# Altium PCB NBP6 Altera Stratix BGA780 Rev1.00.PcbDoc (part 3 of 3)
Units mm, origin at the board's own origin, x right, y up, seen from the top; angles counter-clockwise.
Board outline 69 x 80.99 mm, 6 copper layers (Top Layer, Upper, lower, VCC_PLANE, GND_PLANE, Bottom Layer); 92 components, 279 nets, 1271 pads, 560 vias.
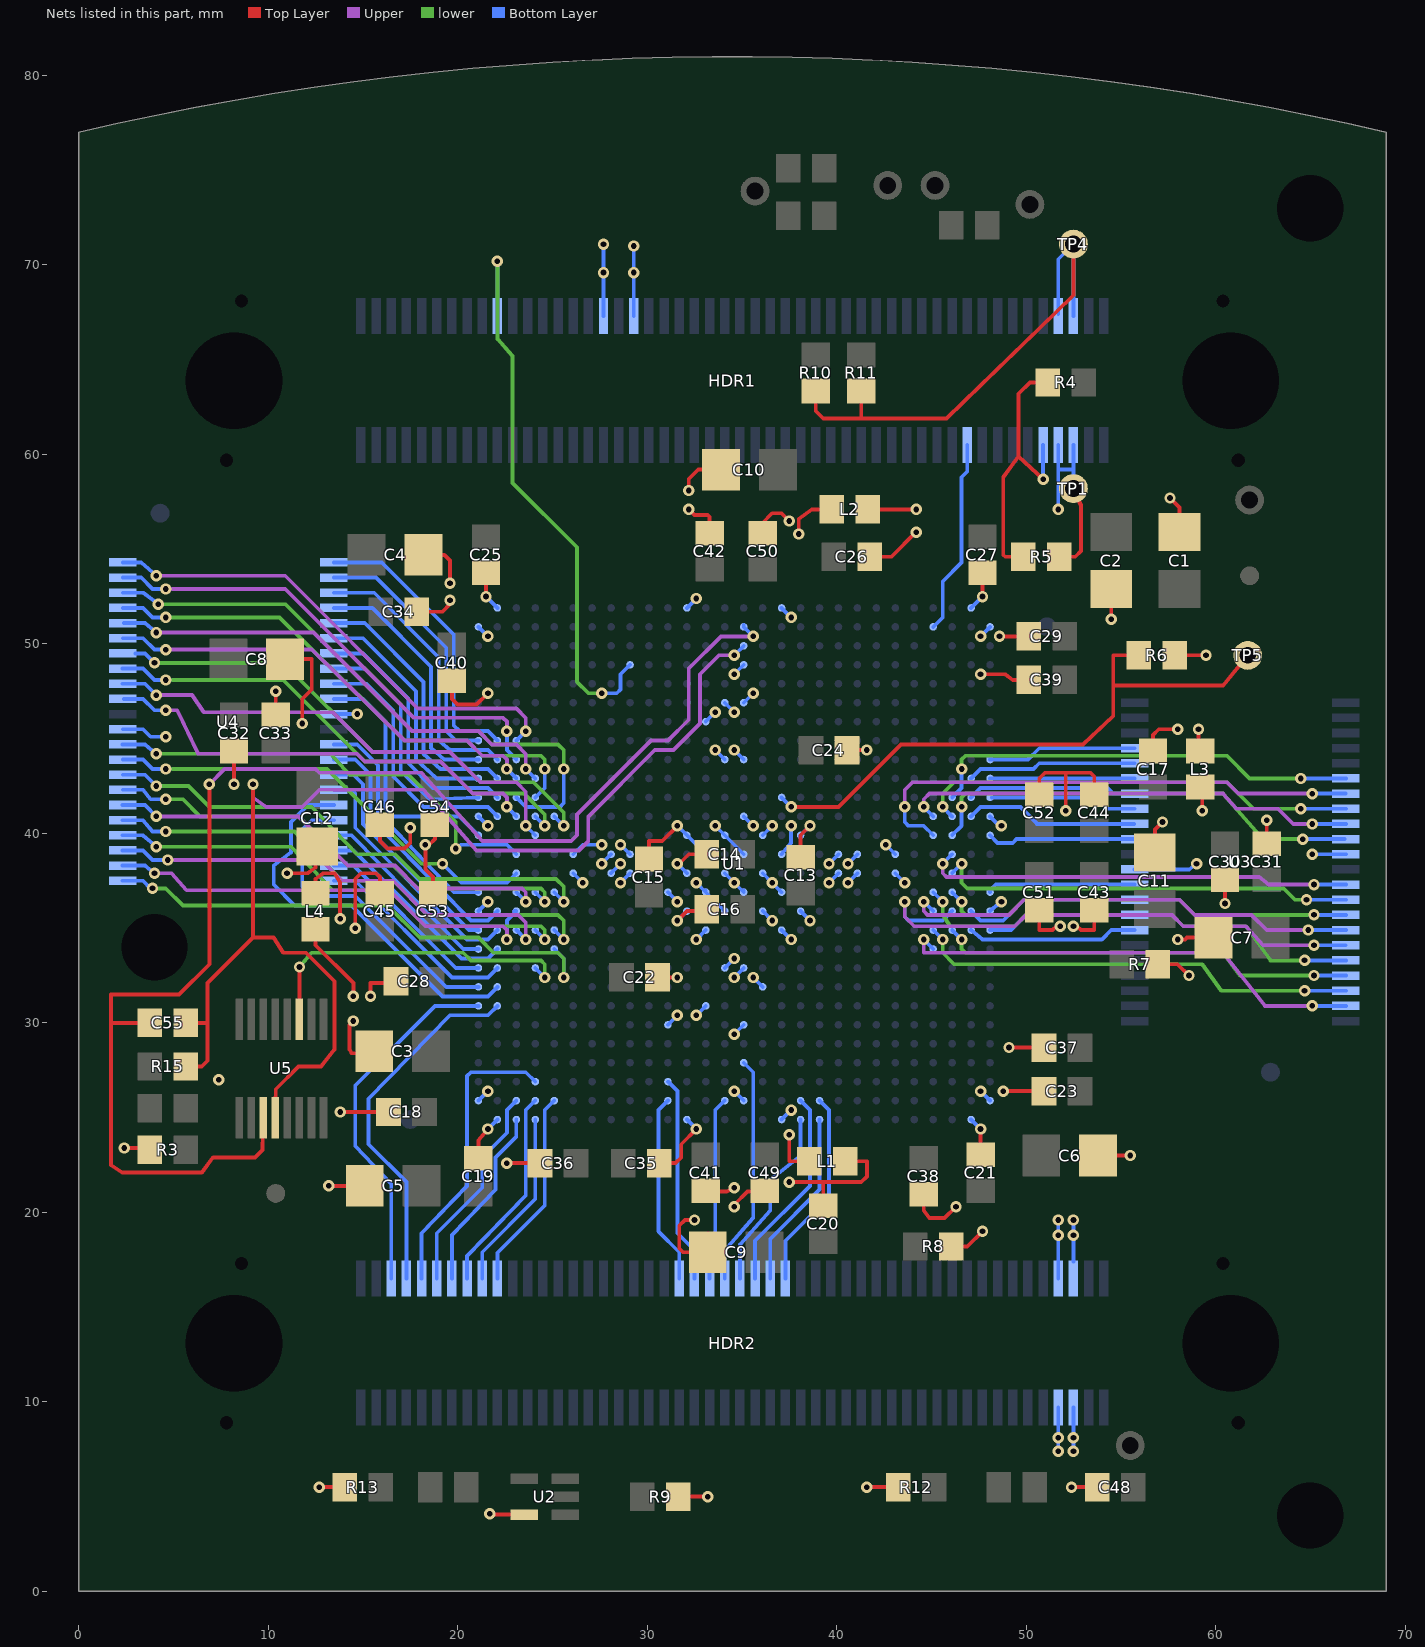
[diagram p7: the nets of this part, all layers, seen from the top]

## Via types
v1: diameter 0.6, hole 0.3, Top Layer to Bottom Layer, 560 vias

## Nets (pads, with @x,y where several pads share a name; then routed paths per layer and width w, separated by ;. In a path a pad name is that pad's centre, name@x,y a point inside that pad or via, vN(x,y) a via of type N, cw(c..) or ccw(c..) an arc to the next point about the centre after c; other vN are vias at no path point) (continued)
SRAM0_A15: U1.W4 U3.21 | length 25.1
  Upper w0.2: v1(44.6,34.4) 44.6,33.7 60.4,33.7 62.6,30.9 v1(65.1,30.9)
  Bottom Layer w0.2: v1(44.6,34.4) U1.W4@45.1,33.9 ; v1(65.1,30.9) U3.21@66.9,30.9
SRAM0_A16: U1.V4 U3.20 | length 23.9
  lower w0.2: v1(45.6,34.4) 45.6,33.7 46.2,33.1 59.3,33.1 60.3,31.7 v1(64.7,31.7)
  Bottom Layer w0.2: U1.V4@45.1,34.9 v1(45.6,34.4) ; v1@64.5,31.7 U3.20@66.9,31.7
SRAM0_A17: U1.V3 U3.19 | length 22.2
  lower w0.2: v1(46.6,34.4) 46.6,33.9 46.8,33.7 60.4,33.7 61.3,32.5 v1(65.2,32.5)
  Bottom Layer w0.2: U1.V3@46.1,34.9 v1(46.6,34.4) ; v1(65.2,32.5) U3.19@66.9,32.5
SRAM0_A18: U1.T4 U3.18 | length 24.4
  lower w0.2: v1(45.6,36.4) 45.6,35.7 46,35.1 49.4,35.1 50,35.7 57.7,35.7 58.3,35.1 61.6,35.1 62.9,33.3 v1(64.7,33.3)
  Bottom Layer w0.2: U1.T4@45.1,36.9 v1(45.6,36.4) ; v1(64.7,33.3) U3.18@66.9,33.3
SRAM0_D0: U1.N4 U3.7 | length 27.2
  Upper w0.2: v1(43.6,41.4) 43.6,42.3 44,42.7 60.6,42.7 61.2,42.1 v1(65.1,42.1)
  Bottom Layer w0.2: v1(43.6,41.4) 43.6,40.6 43.8,40.4 44.6,40.4 U1.N4@45.1,39.9 ; v1(65.1,42.1) U3.7@66.875,42.1
SRAM0_D1: U1.M3 U3.8 | length 23.5
  lower w0.2: v1(45.6,41.4) 45.6,42.1 46.2,42.7 60.6,42.7 62,41.3 v1(64.5,41.3)
  Bottom Layer w0.2: v1(45.6,41.4) U1.M3@46.1,40.9 ; v1(64.5,41.3) U3.8@66.9,41.3
SRAM0_D2: U1.M4 U3.9 | length 24.2
  Upper w0.2: v1(44.6,41.4) 44.6,41.8 44.9,42.1 60.4,42.1 61.1,41.3 63.3,41.3 64.1,40.5 v1(65.1,40.5)
  Bottom Layer w0.2: v1(44.6,41.4) U1.M4@45.1,40.9 ; v1(65.1,40.5) U3.9@66.9,40.5
SRAM0_D3: U1.N3 U3.10 | length 23.6
  lower w0.2: v1(46.6,41.4) 46.6,41.9 46.8,42.1 60.4,42.1 62.5,39.7 v1(64.6,39.7)
  Bottom Layer w0.2: U1.N3@46.1,39.9 46.6,40.4 v1(46.6,41.4) ; v1(64.6,39.7) U3.10@66.8,39.7
SRAM0_D4: U1.P3 U3.13 | length 22.7
  Upper w0.2: v1(45.6,38.4) 45.6,37.9 45.8,37.7 62.3,37.7 62.8,37.3 v1(65.2,37.3)
  Bottom Layer w0.2: v1(45.6,38.4) U1.P3@46.1,38.9 ; v1(65.2,37.3) U3.13@66.9,37.3
SRAM0_D5: U1.R3 U3.14 | length 22.4
  lower w0.2: v1(46.6,38.4) 46.6,37.4 46.9,37.1 63.6,37.1 64.2,36.5 v1(64.8,36.5)
  Bottom Layer w0.2: U1.R3@46.1,37.9 v1(46.6,38.4) ; v1(64.8,36.5) U3.14@66.9,36.5
SRAM0_D6: U1.T3 U3.15 | length 22.3
  lower w0.2: v1(46.6,36.4) 46.6,35.9 46.8,35.7 49.1,35.7 49.9,36.5 58.1,36.5 58.9,35.7 v1(65.2,35.7)
  Bottom Layer w0.2: U1.T3@46.1,36.9 v1(46.6,36.4) ; v1(65.2,35.7) U3.15@66.9,35.7
SRAM0_D7: U1.U4 U3.16 | length 24.6
  Upper w0.2: v1(44.6,36.4) 44.6,35.9 44.8,35.7 49.1,35.7 49.9,36.5 58.1,36.5 58.9,35.7 61.9,35.7 62.7,34.9 v1@64.7,34.9
  Bottom Layer w0.2: v1(44.6,36.4) U1.U4@45.1,35.9 ; v1@64.7,34.9 U3.16@66.9,34.9
  other v1: 64.9,34.9
SRAM0_D8: U1.V2 U3.29 | length 9
  Bottom Layer w0.2: U1.V2@47.1,34.9 47.7,34.4 54,34.4 54.5,34.9 U3.29@55.725,34.9
SRAM0_D9: U1.V1 U3.30 | length 8
  Bottom Layer w0.2: U1.V1@48.1,34.9 49.2,34.9 50,35.7 U3.30@55.725,35.7
SRAM0_D10: U1.U2 U3.31 | length 9.3
  Bottom Layer w0.2: U1.U2@47.1,35.9 47.6,35.4 48.8,35.4 49.9,36.5 U3.31@55.725,36.5
SRAM0_D11: U1.T1 U3.32 | length 7.8
  Bottom Layer w0.2: U1.T1@48.1,36.9 48.1,37 48.4,37.3 U3.32@55.725,37.3
SRAM0_D12: U1.N1 U3.35 | length 7.9
  Bottom Layer w0.2: U1.N1@48.1,39.9 48.5,39.5 49.3,39.5 49.5,39.7 55.625,39.7 U3.35@55.725,39.7
SRAM0_D13: U1.M2 U3.36 | length 9.2
  Bottom Layer w0.2: U1.M2@47.1,40.9 47.6,41.4 49.7,41.4 50.6,40.5 ; 50.575,40.5 U3.36@55.7,40.5
SRAM0_D14: U1.L1 U3.37 | length 7.8
  Bottom Layer w0.2: U1.L1@48.2,41.9 53.7,41.9 54.3,41.3 U3.37@55.725,41.3
SRAM0_D15: U1.L2 U3.38 | length 9
  Bottom Layer w0.2: U1.L2@47.1,41.9 47.6,42.4 54.3,42.4 54.6,42.1 U3.38@55.725,42.1
SRAM0_E: U1.L3 U3.6 | length 23.1
  lower w0.2: v1(46.6,43.4) 46.6,43.9 46.8,44.1 60.6,44.1 61.8,42.9 v1(64.5,42.9)
  Bottom Layer w0.2: U1.L3@46.1,41.9 46.6,42.4 v1(46.6,43.4) ; v1(64.5,42.9) U3.6@66.9,42.9
SRAM0_LB: U1.K1 U3.39 | length 7.6
  Bottom Layer w0.2: U1.K1@48.1,42.9 U3.39@55.725,42.9
SRAM0_OE: U1.J1 U3.41 | length 7.9
  Bottom Layer w0.2: U1.J1@48.1,43.9 50.1,43.9 50.7,44.5 U3.41@55.725,44.5
SRAM0_UB: U1.K2 U3.40 | length 9
  Bottom Layer w0.2: U1.K2@47.1,42.9 47.6,43.4 50.4,43.4 50.7,43.7 U3.40@55.725,43.7
SRAM0_W: U1.U3 U3.17 | length 28.8
  Upper w0.2: v1(43.6,36.4) 43.6,35.6 44.1,35.1 49.4,35.1 50,35.7 57.7,35.7 58.3,35.1 61.6,35.1 62.5,34.1 v1(65.2,34.1)
  Bottom Layer w0.2: v1(43.6,36.4) 43.6,35.6 43.8,35.4 45.6,35.4 U1.U3@46.1,35.9 ; v1(65.2,34.1) U3.17@66.875,34.1
SRAM1_A0: U1.K27 U4.5 | length 14.2
  Bottom Layer w0.2: U4.5@13.475,51.1 15.1,51.1 18.2,48 18.2,44.2 19.1,43.4 21.6,43.4 U1.K27@22.1,42.9
SRAM1_A1: U1.J28 U4.4 | length 13.4
  Bottom Layer w0.2: U4.4@13.475,51.9 15.5,51.9 18.6,48.8 18.6,44.5 19.3,43.9 U1.J28@21.1,43.9
SRAM1_A2: U1.J27 U4.3 | length 14.8
  Bottom Layer w0.2: U4.3@13.475,52.7 15.6,52.7 19,49.3 19,44.9 19.6,44.4 21.6,44.4 U1.J27@22.1,43.9
SRAM1_A3: U1.H28 U4.2 | length 13.8
  Bottom Layer w0.2: U4.2@13.475,53.5 15.7,53.5 19.4,49.8 19.4,45.4 19.9,44.9 U1.H28@21.1,44.9
SRAM1_A4: U1.H27 U4.1 | length 15.3
  Bottom Layer w0.2: U4.1@13.475,54.3 16,54.3 19.8,50.5 19.8,45.7 20.1,45.4 21.6,45.4 U1.H27@22.1,44.9
SRAM1_A5: U1.H26 U4.44 | length 26.1
  Upper w0.2: v1(4.1,53.6) 10.9,53.6 17.9,46.6 23.1,46.6 23.6,46.1 v1(23.6,45.4)
  Bottom Layer w0.2: U4.44@2.325,54.3 3.3,54.3 v1(4.1,53.6) ; U1.H26@23.1,44.9 v1(23.6,45.4)
SRAM1_A6: U1.J26 U4.43 | length 25.7
  Top Layer w0.2: v1(4.6,52.9) v1@4.7,52.9
  Upper w0.2: v1(4.6,52.9) 10.9,52.9 17.7,46.1 22.4,46.1 22.6,45.9 v1(22.6,45.4)
  Bottom Layer w0.2: U4.43@2.325,53.5 3.3,53.5 3.9,52.9 v1(4.6,52.9) ; v1(22.6,45.4) 22.6,44.4 U1.J26@23.1,43.9
SRAM1_A7: U1.L26 U4.42 | length 32.2
  lower w0.2: v1(4.2,52.1) 10.9,52.1 17.6,45.4 21.1,45.4 21.8,44.7 25.3,44.7 25.6,44.4 v1(25.6,43.4)
  Bottom Layer w0.2: U4.42@2.325,52.7 3.4,52.7 v1(4.2,52.1) ; U1.L26@23.1,41.9 23.6,41.4 25.4,41.4 25.6,41.6 v1@25.6,43.3
SRAM1_A8: U1.T26 U4.28 | length 24.4
  Upper w0.2: v1(4.1,40.9) 8.9,40.9 11.6,40.9 14.2,38.3 16.7,38.3 17.9,37.1 23.4,37.1 23.6,36.9 v1(23.6,36.4)
  Bottom Layer w0.2: U4.28@2.3,41.5 3.5,41.5 v1(4.1,40.9) ; U1.T26@23.1,36.9 v1(23.6,36.4)
SRAM1_A9: U1.V24 U4.27 | length 27.3
  lower w0.2: v1(4.6,40.1) 11.4,40.1 13.9,37.5 16.6,37.5 18.4,35.7 25.3,35.7 25.6,35.4 v1(25.6,34.4)
  Bottom Layer w0.2: U4.27@2.3,40.7 3.4,40.7 3.9,40.1 v1(4.6,40.1) ; U1.V24@25.1,34.9 v1(25.6,34.4)
SRAM1_A10: U1.V25 U4.26 | length 25.6
  lower w0.2: v1(4.1,39.3) 11.2,39.3 13.4,37 16.4,37 18.3,35.1 24.4,35.1 24.6,34.9 v1(24.6,34.4)
  Bottom Layer w0.2: U4.26@2.3,39.9 3.4,39.9 v1(4.1,39.3) ; U1.V25@24.1,34.9 v1(24.6,34.4)
SRAM1_A11: U1.V26 U4.25 | length 24.5
  Upper w0.2: v1(4.7,38.6) 12.8,38.6 13.9,37.5 16.6,37.5 18.4,35.7 23.2,35.7 23.6,35.3 v1(23.6,34.4)
  Bottom Layer w0.2: U4.25@2.3,39.1 3.4,39.1 3.9,38.6 v1(4.7,38.6) ; U1.V26@23.1,34.9 v1(23.6,34.4)
SRAM1_A12: U1.U26 U4.24 | length 24
  Upper w0.2: v1(4,37.9) 4.9,37.9 5.7,37 12.9,37 16.4,37 18.3,35.1 22.4,35.1 22.6,34.9 v1(22.6,34.4)
  Bottom Layer w0.2: U4.24@2.3,38.3 3.5,38.3 v1(4,37.9) ; v1(22.6,34.4) 22.6,35.4 U1.U26@23.1,35.9 U1.U26@23,35.9
SRAM1_A13: U1.W24 U4.23 | length 35.9
  lower w0.2: v1(3.9,37.1) 4.6,37.1 5.5,36.2 16.3,36.2 ; v1(25.6,32.4) 25.6,33.4 25.3,33.7 21.9,33.7 21.1,34.5 18,34.5 16.3,36.2 ; 16.3,36.2 12.2,36.2 16.3,36.2
  Bottom Layer w0.2: U4.23@2.3,37.5 3.4,37.5 3.8,37.1 v1(3.9,37.1) ; U1.W24@25.1,33.9 25.6,33.4 v1(25.6,32.4)
SRAM1_A14: U1.Y27 U4.22 | length 10.9
  Bottom Layer w0.2: U4.22@13.475,37.5 14.6,37.5 19.7,32.4 21.6,32.4 U1.Y27@22.1,32.9
SRAM1_A15: U1.Y28 U4.21 | length 9.9
  Bottom Layer w0.2: U4.21@13.475,38.3 14.5,38.3 19.9,32.9 U1.Y28@21.1,32.9
SRAM1_A16: U1.W27 U4.20 | length 11.2
  Bottom Layer w0.2: U4.20@13.475,39.1 14.5,39.1 20.2,33.4 21.6,33.4 U1.W27@22.1,33.9
SRAM1_A17: U1.W28 U4.19 | length 10.1
  Bottom Layer w0.2: U4.19@13.475,39.9 13.575,39.9 14.4,39.9 20.3,33.9 U1.W28@21.1,33.9
SRAM1_A18: U1.AA28 U4.18 | length 16.4
  Bottom Layer w0.2: U4.18@13.475,40.7 12.3,40.7 11.8,40.2 11.8,37.2 12.275,36.725 12.275,36.7 14.6,36.7 19.4,31.9 U1.AA28@21.1,31.9
SRAM1_D0: U1.L27 U4.7 | length 13.8
  Bottom Layer w0.2: U4.7@13.475,49.5 15,49.5 17.4,47.1 17.4,43.7 18.7,42.4 21.6,42.4 U1.L27@22.1,41.9
SRAM1_D1: U1.L28 U4.8 | length 12.5
  Bottom Layer w0.2: U4.8@13.475,48.7 15.1,48.7 17,46.8 17,43.3 18.5,41.8 U1.L28@21.1,41.9
SRAM1_D2: U1.M27 U4.9 | length 13.6
  Bottom Layer w0.2: U4.9@13.475,47.9 15.2,47.9 16.6,46.5 16.6,43 18.2,41.4 21.6,41.4 U1.M27@22.1,40.9
SRAM1_D3: U1.N28 U4.10 | length 13.3
  Bottom Layer w0.2: U4.10@13.475,47.1 15,47.1 16.2,45.9 16.2,41.3 16.6,40.9 20.1,40.9 U1.N28@21.1,39.9
SRAM1_D4: U1.T28 U4.13 | length 12.4
  Bottom Layer w0.2: U4.13@13.475,44.7 14.7,44.7 15.8,43.6 15.8,41.1 19.8,36.9 U1.T28@21.1,36.9
SRAM1_D5: U1.U27 U4.14 | length 13.7
  Bottom Layer w0.2: U4.14@13.475,43.9 14.6,43.9 15.4,43.1 15.4,40.8 20.7,35.4 21.6,35.4 U1.U27@22.1,35.9
SRAM1_D6: U1.V28 U4.15 | length 12.3
  Bottom Layer w0.2: U4.15@13.475,43.1 14.5,43.1 15,42.6 15,40.5 20.6,34.9 U1.V28@21.1,34.9
SRAM1_D7: U1.V27 U4.16 | length 13.2
  Bottom Layer w0.2: U4.16@13.475,42.3 14.4,42.3 14.6,42.1 14.6,40.3 20.5,34.4 21.6,34.4 U1.V27@22.1,34.9
SRAM1_D8: U1.T25 U4.29 | length 25.7
  lower w0.2: v1(4.6,41.8) 5.5,41.8 6.4,40.9 11.6,40.9 14.2,38.3 16.6,38.3 17.9,37.1 24.4,37.1 24.6,36.9 v1(24.6,36.4)
  Bottom Layer w0.2: U4.29@2.325,42.3 3.4,42.3 3.8,41.8 v1(4.6,41.8) ; U1.T25@24.1,36.9 v1(24.6,36.4)
SRAM1_D9: U1.T24 U4.30 | length 27.3
  lower w0.2: v1(4.1,42.5) 5.8,42.5 6.9,41.4 12.3,41.4 14.7,38.9 16.7,38.9 18,37.6 25.2,37.6 25.6,37.2 v1(25.6,36.4)
  Bottom Layer w0.2: U4.30@2.325,43.1 3.5,43.1 v1(4.1,42.5) ; U1.T24@25.1,36.9 v1(25.6,36.4)
SRAM1_D10: U1.R26 U4.31 | length 23.7
  lower w0.2: v1(4.6,43.4) 13.1,43.4 18.1,38.4 v1(19.2,38.4)
  Bottom Layer w0.2: U4.31@2.325,43.9 3.4,43.9 3.9,43.4 v1(4.6,43.4) ; v1(19.2,38.4) 20.2,37.4 22.6,37.4 U1.R26@23.1,37.9
SRAM1_D11: U1.P26 U4.32 | length 24.2
  lower w0.2: v1(4.1,44.2) 13.3,44.2 14.3,43.1 17.4,43.1 19.9,40.6 v1(19.9,39.2)
  Bottom Layer w0.2: U4.32@2.3,44.7 3.5,44.7 v1(4.1,44.2) ; v1(19.9,39.2) 20.2,39.4 22.6,39.4 U1.P26@23.1,38.9
SRAM1_D12: U1.M26 U4.35 | length 24
  Upper w0.2: v1@4.584,46.516 4.6,46.516 5.2,46.5 6.3,44.2 9,44.2 14.7,44.2 15.1,43.8 19.1,43.8 20.8,42.1 22.4,42.1 22.6,41.9 v1(22.6,41.4)
  Bottom Layer w0.2: U4.35@2.4,47.1 3.4,47.1 4,46.5 v1@4.5,46.5 ; v1(22.6,41.4) U1.M26@23.1,40.9
  other v1: 4.6,46.5
SRAM1_D13: U1.N25 U4.36 | length 26.4
  Top Layer w0.2: v1@4,47.3 v1(4.1,47.3)
  Upper w0.2: v1(4.1,47.3) 6,47.3 6.6,46.4 13.4,46.4 15.5,44.3 19.6,44.3 21.2,42.7 23.1,42.7 23.6,42.2 v1(23.6,40.4)
  Bottom Layer w0.2: U4.36@2.3,47.9 3.5,47.9 v1(4.1,47.3) ; v1(23.6,40.4) U1.N25@24.1,39.9
SRAM1_D14: U1.M25 U4.37 | length 26.8
  lower w0.2: v1(4.6,48.1) 10.8,48.1 15.1,43.8 19.1,43.8 20.8,42.1 23.5,42.1 24.6,41 v1(24.6,40.4)
  Bottom Layer w0.2: U4.37@2.3,48.7 3.4,48.7 4,48.1 v1(4.6,48.1) ; U1.M25@24.1,40.9 v1(24.6,40.4)
SRAM1_D15: U1.M24 U4.38 | length 27.5
  lower w0.2: v1(4,49) 10.8,49 15.5,44.3 19.6,44.3 21.2,42.7 24,42.7 25.6,41.1 v1(25.6,40.4)
  Bottom Layer w0.2: U4.38@3,49.5 3.5,49.5 v1(4,49) ; U1.M24@25.1,40.9 v1(25.6,40.4)
SRAM1_E: U1.K28 U4.6 | length 12.8
  Bottom Layer w0.2: U4.6@13.475,50.3 15,50.3 17.8,47.5 17.8,43.9 18.9,42.9 U1.K28@21.1,42.9
SRAM1_LB: U1.K26 U4.39 | length 24.1
  Upper w0.2: v1(4.6,49.7) 12.3,49.7 17.2,44.9 20.5,44.9 21.3,44.1 22.4,44.1 22.6,43.9 22.6,43.8 v1(22.6,43.4)
  Bottom Layer w0.2: U4.39@2.325,50.3 3.4,50.3 4,49.7 v1(4.6,49.7) ; v1(22.6,43.4) U1.K26@23.1,42.9
SRAM1_OE: U1.L25 U4.41 | length 27.8
  lower w0.2: v1(4.6,51.4) 10.6,51.4 17.2,44.9 20.5,44.9 21.3,44.1 24.4,44.1 24.6,43.9 v1(24.6,43.4)
  Bottom Layer w0.2: U4.41@2.325,51.9 3.4,51.9 3.9,51.4 v1(4.6,51.4) ; U1.L25@24.1,41.9 24.6,42.4 v1(24.6,43.4)
SRAM1_UB: U1.K25 U4.40 | length 25.5
  Upper w0.2: v1(4.1,50.6) 12.4,50.6 17.6,45.4 21.1,45.4 21.8,44.7 23.1,44.7 23.6,44.2 v1(23.6,43.4)
  Bottom Layer w0.2: U4.40@2.4,51.1 3.5,51.1 v1(4.1,50.6) ; v1(23.6,43.4) U1.K25@24.1,42.9
SRAM1_W: U1.AA27 U4.17 | length 21.1
  Bottom Layer w0.2: U4.17@13.475,41.5 12.1,41.5 11.2,40.6 11.2,39 10.3,38.3 10.3,37.3 11.4,36.2 14.4,36.2 19.2,31.4 21.6,31.4 U1.AA27@22.1,31.9 ; U1.AA27@22.1,31.9 22,31.8 U1.AA27@22.1,31.9
SW0: HDR2.44 U1.AG18 | length 10.1
  Bottom Layer w0.2: U1.AG18@31.1,25.9 30.6,25.4 30.6,19 31.7,17.9 HDR2.44@31.7,16.5
SW1: HDR2.46 U1.AF18 | length 11
  Bottom Layer w0.2: U1.AF18@31.1,26.9 31.6,26.4 31.6,18.9 32.5,18 HDR2.46@32.5,16.5
SW2: HDR2.48 U1.AG15 | length 9.7
  Bottom Layer w0.2: HDR2.48@33.3,16.5 33.3,17.9 33.6,18.2 33.6,25.4 U1.AG15@34.1,25.9
SW3: HDR2.50 U1.AE14 | length 12.2
  Bottom Layer w0.2: HDR2.50@34.1,16.5 34.1,18 35.6,19.7 35.6,27.4 U1.AE14@35.1,27.9
SW4: HDR2.52 U1.AH11 | length 9.8
  Bottom Layer w0.2: HDR2.52@34.9,16.5 34.9,18.3 36.5,20.1 36.5,21.7 38.1,23 U1.AH11@38.1,24.9
SW5: HDR2.54 U1.AG11 | length 10.8
  Bottom Layer w0.2: HDR2.54@35.7,16.5 35.7,18.5 38.6,21.4 38.6,25.4 U1.AG11@38.1,25.9
SW6: HDR2.56 U1.AH10 | length 9.5
  Bottom Layer w0.2: HDR2.56@36.5,16.5 36.5,18.6 39.1,21.2 U1.AH10@39.1,24.9
SW7: HDR2.58 U1.AG10 | length 10.6
  Bottom Layer w0.2: HDR2.58@37.3,16.5 37.3,18.5 39.6,20.8 39.6,25.4 U1.AG10@39.1,25.9
SWC0: HDR2.18 U1.AH25 | length 9.6
  Bottom Layer w0.2: HDR2.18@21.3,16.5 21.3,17.9 24.1,20.7 U1.AH25@24.1,24.9
SWC1: HDR2.16 U1.AG25 | length 13.6
  Bottom Layer w0.2: HDR2.16@20.5,16.5 20.5,17.7 23.6,20.9 23.6,25.4 ; 23.6,22.7 23.6,25.4 ; U1.AG25@24.1,25.9 23.6,25.4
SWC2: HDR2.14 U1.AH26 | length 9.8
  Bottom Layer w0.2: HDR2.14@19.7,16.5 19.7,18.7 19.7,18.8 22,21.2 22,22.9 23.1,24 U1.AH26@23.1,24.9
SWC3: HDR2.6 U1.AB28 | length 19.2
  Bottom Layer w0.2: HDR2.6@16.5,16.5 16.5,21.5 14.6,23.5 14.6,26.7 18.8,30.9 U1.AB28@21.1,30.9
SWR0: HDR2.20 U1.AG24 | length 10.6
  Bottom Layer w0.2: HDR2.20@22.1,16.5 22.1,17.871 24.6,20.371 24.6,25.4 U1.AG24@25.1,25.9
SWR1: HDR2.12 U1.AG26 | length 11.1
  Bottom Layer w0.2: HDR2.12@18.9,16.5 18.9,18.9 21.3,21.3 21.3,22.9 22.6,24.2 22.6,25.4 U1.AG26@23.1,25.9
SWR2: HDR2.10 U1.AF25 | length 15.6
  Bottom Layer w0.2: HDR2.10@18.1,16.5 18.1,18.9 20.5,21.4 20.5,27.2 20.7,27.4 23.6,27.4 U1.AF25@24.1,26.9
SWR3: HDR2.8 U1.AB27 | length 19.2
  Bottom Layer w0.2: HDR2.8@17.3,16.5 17.3,21.6 15.3,23.6 15.3,26 19.6,30.4 21.6,30.4 U1.AB27@22.1,30.9
TEMP_ALERT: U1.Y25 U5.11 | length 17.7
  Top Layer w0.2: U5.11@11.652,30.2 v1(11.652,32.948)
  lower w0.2: v1(11.652,32.948) 12.3,33.7 20.3,33.7 20.7,33.3 24.4,33.3 24.6,33.1 v1(24.6,32.4)
  Bottom Layer w0.2: U1.Y25@24.1,32.9 v1(24.6,32.4)
TEMPDIODEN: C55.1 R15.2 U1.C14 U5.4 | length 66.8
  Top Layer w0.2: C55.1@5.6,30 6.8,30 ; R15.2@5.65,27.7 6.5,27.7 6.8,28 6.8,32.1 9.2,34.5 ; v1(9.2,42.6) 9.2,34.5 ; 10.382,26.1 10.4,26.2 10.4,26.5 11.6,27.7 12.8,27.7 13.5,28.6 13.5,32.2 12,33.7 10.8,33.7 10.3,34.5 9.2,34.5
  Upper w0.2: v1(9.2,42.6) 9.2,41.9 9.9,41.4 11.8,41.4 12.7,42.3 18.2,42.3 21,39.1 26.4,39.1 26.9,39.6 26.9,40.9 30.4,44.4 31.4,44.4 32.8,45.8 32.8,48.4 33.8,49.4 v1(34.6,49.4)
  Bottom Layer w0.2: v1(34.6,49.4) U1.C14@35.1,49.9
TEMPDIODEP: C55.2 U1.B14 U5.3 | length 75.1
  Top Layer w0.2: 1.7,30 C55.2@3.8,30 ; v1(6.9,42.6) 6.9,33.1 5.3,31.5 1.7,31.5 1.7,22.5 2.3,22.1 6.5,22.1 7.1,22.9 9.3,22.9 9.7,23.3 U5.3@9.747,25
  Upper w0.2: v1(6.9,42.6) 7.7,43.4 12.5,43.4 12.7,43.2 18.1,43.2 21.3,39.6 26,39.6 26.3,39.9 26.3,41 30.2,44.9 31.1,44.9 32.2,46 32.2,48.7 33.9,50.4 v1(35.6,50.4)
  Bottom Layer w0.2: U1.B14@35.1,51 U1.B14@35.1,50.9 v1(35.6,50.4)
TEST: HDR1.81 U1.B4 | length 10.3
  Bottom Layer w0.2: U1.B4@45.1,50.9 45.6,51.4 45.6,52.6 45.6,53.3 46.6,54.3 46.6,58.6 46.6,58.8 46.9,59.1 HDR1.81@46.9,60.5
TRST: R6.2 TP5.1 U1.L12 | length 32.1
  Top Layer w0.2: v1(37.6,41.4) 40.1,41.4 43.4,44.7 53,44.7 54.6,46.2 54.6,49.4 R6.2@55.95,49.4 ; 54.6,47.8 60.4,47.8 TP5.1@61.7,49.4
  Bottom Layer w0.2: U1.L12@37.1,41.9 v1(37.6,41.4)
VCC: C2.1 C4.1 C5.1 C6.1 C7.1 C8.1 C18.1 C19.1 C21.1 C23.1 C25.1 C27.1 C29.1 C30.1 C31.1 C32.1 C33.1 C34.1 C35.1 C36.1 C37.1 C38.1 C39.1 C40.1 C48.1 HDR1.34 HDR1.38 HDR1.94 HDR1.96 HDR2.94 HDR2.96 R3.1 R6.1 R7.1 R8.2 R9.1 R10.1 R11.1 R12.1 R13.1 TP4.1 U1.A2 U1.A12 U1.A17 U1.A27 U1.AA13 U1.AB16 U1.AC14 U1.AC18 U1.AG1 U1.AG28 U1.AH2 U1.AH12 U1.AH17 U1.AH27 U1.B1 U1.B28 U1.D14 U1.F15 U1.G16 U1.J14 U1.J15 U1.M1 U1.M28 U1.P8 U1.P9 U1.P20 U1.P21 U1.R8 U1.R9 U1.R20 U1.R21 U1.U1 U1.U28 U1.Y14 U1.Y15 U2.5 U3.11 U3.33 U4.11 U4.33 | length 139.1
  Top Layer w0.2: v1(2.4,23.4) R3.1@3.7,23.4 ; v1(8.2,42.6) C32.1@8.2,44.35 ; C33.1@10.4,46.25 v1(10.4,47.5) ; C8.1@10.9,49.2 12.3,49.2 12.3,47.6 11.8,47.1 v1(11.8,45.8) ; v1(12.7,5.5) R13.1@14.05,5.5 ; v1(13.2,21.4) C5.1@15.1,21.4 ; v1(13.8,25.3) C18.1@16.3,25.3 ; C34.1@17.85,51.7 19.2,51.7 19.6,52.1 v1(19.6,52.3) ; C4.1@18.2,54.7 19.3,54.7 19.6,54.4 v1(19.6,53.2) ; C40.1@19.7,48.05 19.7,47.1 20,46.8 21,46.8 v1(21.6,47.4) ; C19.1@21.1,22.85 21.1,23.8 v1(21.6,24.4) ; v1@21.5,52.75 C25.1@21.5,53.75 ; v1(21.7,4.1) 21.75,4.05 U2.5@23.525,4.05 ; v1@22.8,22.6 23.4,22.6 C36.1@24.35,22.6 ; C35.1@30.6,22.6 31.5,22.6 31.8,22.9 31.8,23.6 v1(32.6,24.4) ; R9.1@31.8,5 v1(33.2,5) ; R10.1@38.9,63.35 38.9,62.3 39.3,61.9 45.8,61.9 52.5,68.4 TP4.1@52.5,71.1 ; 41.3,61.9 R11.1@41.3,63.35 ; v1(41.6,5.5) R12.1@43.25,5.5 ; C38.1@44.6,20.95 44.6,20.1 44.9,19.7 45.7,19.7 v1(46.3,20.3) ; R8.2@46.35,18.2 46.9,18.2 v1(47.7,19) ; v1@47.6,24.2 C21.1@47.6,23.05 C21.1@47.7,23.15 ; v1(47.6,48.4) 48.9,48.4 49.3,48.1 C39.1@50.15,48.1 ; v1(47.7,52.5) C27.1@47.7,53.8 ; v1(48.6,50.4) C29.1@50.15,50.4 ; v1(48.8,26.4) C23.1@50.9,26.4 ; v1@49.4,28.7 C37.1@50.5,28.7 ; v1(52.4,5.5) C48.1@53.7,5.5 ; C6.1@53.7,23 v1@55.3,23 ; v1(54.5,51.3) C2.1@54.5,52.9 ; R7.1@56.95,33.1 58,33.1 v1(58.6,32.5) ; R6.1@57.85,49.4 v1(59.5,49.4) ; v1(58,34.4) 58.4,34.4 58.5,34.5 C7.1@59.9,34.5 ; v1(60.5,36.3) C30.1@60.5,37.55 ; C31.1@62.7,39.45 v1(62.7,40.7)
  Bottom Layer w0.2: U4.33@2.325,45.5 3.4,45.5 3.8,45.1 v1(4.6,45.1) ; U4.11@13.475,46.3 v1(14.7,46.3) ; U1.AG28@21.1,25.9 v1(21.6,26.4) ; U1.U28@21.1,35.9 v1(21.6,36.4) ; U1.M28@21.1,40.9 v1(21.6,40.4) ; U1.B28@21.1,50.9 v1(21.6,50.4) ; v1(21.5,52.5) U1.A27@22.1,51.9 ; v1(21.6,24.4) U1.AH27@22.1,24.9 ; v1(27.6,38.4) U1.P21@28.1,38.9 ; HDR1.34@27.7,67.3 v1(27.7,69.6) v1(27.7,71.1) ; U1.R21@28.1,37.9 v1(28.6,38.4) ; v1(28.6,37.4) U1.R20@29.1,37.9 ; v1(28.6,39.4) U1.P20@29.1,38.9 ; HDR1.38@29.3,67.3 v1(29.3,71) ; U1.AC18@31.1,29.9 v1(31.6,30.4) ; U1.AH17@32.1,24.9 v1(32.6,24.4) ; U1.A17@32.1,51.9 v1(32.6,52.4) ; v1(32.6,30.4) U1.AB16@33.1,30.9 ; U1.G16@33.1,45.9 v1(33.6,46.4) ; v1(33.6,44.4) U1.J15@34.1,43.9 ; U1.Y15@34.1,32.9 v1(34.6,33.4) ; U1.F15@34.1,46.9 v1(34.6,46.4) ; v1(34.6,29.4) U1.AC14@35.1,29.9 ; v1(34.6,32.4) U1.Y14@35.1,32.9 ; v1(34.6,44.4) U1.J14@35.1,43.9 ; v1(34.6,48.4) U1.D14@35.1,48.9 ; v1(35.6,32.4) U1.AA13@36.1,31.9 ; U1.AH12@37.1,24.9 v1(37.6,25.4) ; U1.A12@37.1,51.9 v1(37.6,51.4) ; v1(39.6,37.4) U1.R9@40.1,37.9 ; v1(39.6,38.4) U1.P9@40.1,38.9 ; v1(40.6,37.4) U1.R8@41.1,37.9 ; v1(40.6,38.4) U1.P8@41.1,38.9 ; U1.AH2@47.1,24.9 v1(47.6,24.4) v1@47.6,24.2 ; U1.A2@47.1,51.9 v1(47.7,52.5) ; v1(47.6,26.4) U1.AG1@48.1,25.9 ; v1(47.6,50.4) U1.B1@48.1,50.9 ; U1.U1@48.1,35.9 v1(48.7,36.4) ; U1.M1@48.1,40.9 48.6,40.4 v1(48.7,40.4) ; HDR2.94@51.7,16.5 v1(51.7,19.6) ; HDR1.94@51.7,67.4 51.7,69.7 51.7,70.3 TP4.1@52.5,71.1 HDR1.96@52.5,67.3 ; HDR2.96@52.5,17.4 v1(52.5,19.6) ; U3.33@55.725,38.1 58,38.1 58.6,38.1 v1(59,38.4) ; v1(65.1,38.9) U3.11@66.9,38.9
  other v1: 51.7,18.8 52.5,18.8 22.6,22.6 55.5,23 7.4,27 49.1,28.7 29.3,69.6
VCCA_PLL1: C12.1 C45.1 C46.1 C53.1 C54.1 L4.2 U1.P23 U1.R23 | length 22.1
  Top Layer w0.2: v1@11,37.7 v1(11,37.9) 12.1,37.9 12.5,38.2 C12.1@12.5,39.1 ; L4.2@12.5,36.85 12.5,37.6 12.9,37.9 13.5,37.9 13.8,37.4 v1(13.8,35.5) ; v1(14.6,35) 14.6,37.6 14.9,37.9 15.7,37.9 15.9,37.7 C45.1@15.9,36.85 ; C46.1@15.9,40.45 15.9,39.6 16.3,39.2 17.2,39.2 17.5,39.5 v1(17.5,40.3) ; C53.1@18.7,36.85 18.7,37.7 18.3,38.1 v1(18.3,39.4) 18.5,39.4 18.8,39.7 C54.1@18.8,40.5
  Bottom Layer w0.2: U1.R23@26.1,37.9 v1(26.6,37.4) ; U1.P23@26.1,38.9 26.6,39.4 v1(27.6,39.4)
VCCA_PLL3: C11.1 C43.1 C44.1 C51.1 C52.1 L3.2 U1.P6 U1.R6 | length 15.7
  Top Layer w0.2: C51.1@50.7,35.95 50.7,34.9 51.4,34.9 51.6,35.1 v1(51.8,35.1) ; C52.1@50.7,42.05 50.7,42.9 51,43.2 53.4,43.2 53.6,43 C44.1@53.6,42.05 ; v1(52.1,41.2) 52.1,43.2 ; v1(52.5,35.1) 52.7,35.1 52.9,34.9 53.6,34.9 C43.1@53.6,35.95 ; C11.1@56.8,39.1 56.8,40.2 v1(57.2,40.6) ; v1(59.3,41.2) L3.2@59.3,42.45
  Bottom Layer w0.2: v1(42.6,39.4) U1.P6@43.1,38.9 ; U1.R6@43.1,37.9 v1(43.6,37.4)
VCCA_PLL5: C10.1 C42.1 C50.1 L2.2 U1.F14 | length 10.6
  Top Layer w0.2: v1(32.2,57.1) 32.5,56.8 33.2,56.8 33.3,56.7 C42.1@33.3,55.9 ; v1(32.2,58.1) 32.2,58.7 32.7,59.2 C10.1@33.9,59.2 ; C50.1@36.1,55.8 36.1,56.4 36.6,56.9 37.1,56.9 37.6,56.4 v1(37.51,56.49) ; v1(38,55.8) 38,56.6 38.7,57.1 L2.2@39.75,57.1
  Bottom Layer w0.2: U1.F14@35.1,46.9 v1(35.6,47.4)
VCCA_PLL6: C9.1 C41.1 C49.1 L1.2 U1.AG14 | length 11.4
  Top Layer w0.2: v1(32.5,19.6) 32,19.6 31.7,19.3 31.7,18.1 31.9,17.9 C9.1@33.2,17.9 C9.1@33.2,18.9 ; C41.1@33.1,21.1 34.2,21.1 v1(34.6,21.3) ; v1(34.6,20.3) 34.6,20.4 35.3,21.1 C49.1@36.2,21.1 ; v1(37.5,24.1) 37.5,22.7 L1.2@38.55,22.7
  Bottom Layer w0.2: v1(34.6,26.4) U1.AG14@35.1,25.9
VCCINT: C1.1 C3.1 C13.1 C14.1 C15.1 C16.1 C17.1 C20.1 C22.1 C24.1 C26.1 C28.1 HDR1.93 HDR1.95 HDR2.93 HDR2.95 L1.1 L2.1 L3.1 L4.1 R5.1 TP1.1 U1.M14 U1.N11 U1.N13 U1.N15 U1.N17 U1.P12 U1.P14 U1.P16 U1.R13 U1.R15 U1.R17 U1.T12 U1.T14 U1.T16 U1.T18 U1.U11 U1.U13 U1.U15 U1.U17 U1.V12 U1.V16 | length 71.9
  Top Layer w0.2: L4.1@12.5,34.95 12.5,34.1 14.5,32.1 v1(14.5,31.4) ; v1(14.5,30.1) 14.3,29.9 14.3,28.6 14.4,28.4 C3.1@15.6,28.4 ; v1(15.4,31.4) 15.4,32.1 15.7,32.1 C28.1@16.7,32.1 ; C15.1@30.1,38.65 30.1,39.6 30.8,39.6 v1(31.6,40.4) ; C22.1@30.6,32.4 v1(31.6,32.4) ; v1(31.6,35.4) 32.1,35.9 C16.1@33.15,35.9 ; v1(31.6,38.4) 31.7,38.4 32.2,38.9 C14.1@33.15,38.9 ; v1(37.5,21.6) 41.3,21.6 41.6,21.9 41.6,22.7 L1.1@40.45,22.7 ; C13.1@38.1,38.75 38.1,39.9 v1(38.6,40.4) ; C20.1@39.3,20.35 39.3,21.6 ; C24.1@40.6,44.4 v1(41.6,44.4) ; L2.1@41.7,57.1 v1(44.2,57.1) ; C26.1@41.75,54.6 42.9,54.6 v1(44.2,55.9) ; R5.1@51.7,54.65 R5.1@51.75,54.6 52.6,54.6 52.9,54.9 52.9,56.5 52.9,57.3 TP1.1@52.5,58.2 ; C17.1@56.7,44.4 56.7,45.2 57,45.5 v1(58,45.5) ; v1(57.6,57.7) 58.1,57.2 C1.1@58.1,55.9 ; L3.1@59.1,44.35 v1(59.1,45.5)
  Bottom Layer w0.2: U1.T18@31.1,36.9 v1(31.6,36.4) ; v1(31.6,35.4) U1.U17@32.1,35.9 ; v1(31.6,38.4) U1.R17@32.1,37.9 ; v1(31.6,40.4) U1.N17@32.1,39.9 U1.P16@33.1,38.9 ; v1(32.6,34.4) U1.V16@33.1,34.9 ; v1(32.6,37.4) U1.T16@33.1,36.9 ; U1.T16@33.1,37 U1.T16@33.1,36.9 ; v1(33.6,40.4) U1.N15@34.1,39.9 U1.P14@35.1,38.9 ; U1.U15@34.1,35.9 U1.T16@33.1,36.9 ; U1.R15@34.1,37.9 v1(34.6,37.4) ; v1@34.7,37.4 v1(34.6,37.4) ; U1.T14@35.1,37 U1.T14@35.1,36.9 v1(34.6,37.4) ; U1.M14@35.1,40.9 v1(35.6,40.4) ; U1.U13@36.1,35.9 v1(36.6,35.4) ; U1.R13@36.1,37.9 v1(36.6,37.4) U1.T12@37.1,36.9 ; U1.N13@36.1,39.9 v1(36.6,40.4) ; U1.V12@37.1,34.9 v1(37.6,34.4) ; U1.P12@37.1,38.9 37.6,39.5 v1(37.6,40.4) ; U1.U11@38.1,35.9 v1(38.6,35.4) ; U1.N11@38.1,39.9 v1(38.6,40.4) ; v1(51.7,7.4) v1(51.7,8.1) HDR2.93@51.7,9.7 ; v1(51.7,57.1) HDR1.93@51.7,60.5 ; 51.7,59.2 52.5,59.2 ; v1(52.5,7.4) v1(52.5,8.1) HDR2.95@52.5,9.7 ; TP1.1@52.5,58.2 52.5,59.5 HDR1.95@52.5,60.5
VDRIVE: HDR1.20 U1.D20 | length 31
  lower w0.2: v1(22.1,70.2) 22.1,66.1 22.9,65.2 22.9,58.5 26.3,55.1 26.3,48 26.9,47.4 v1(27.6,47.4)
  Bottom Layer w0.2: HDR1.20@22.1,67.3 v1(22.1,70.2) ; v1(27.6,47.4) 28.4,47.4 28.6,47.6 28.6,48.4 U1.D20@29.1,48.9
VREF: HDR1.91 R4.1 R5.2 | length 15.4
  Top Layer w0.2: R5.2@49.85,54.6 48.9,54.6 48.8,54.7 48.8,58.8 49.6,59.9 ; v1(50.9,58.7) 49.6,59.9 ; R4.1@51.15,63.8 50.2,63.8 49.6,63.2 49.6,59.9
  Bottom Layer w0.2: v1(50.9,58.7) 50.9,58.6 HDR1.91@50.9,60.5
pads on no net: HDR1.MH1 HDR1.MH2 HDR1.MH3 HDR1.MH4 HDR1.MH5 HDR1.MH6 HDR2.MH1 HDR2.MH2 HDR2.MH3 HDR2.MH4 HDR2.MH5 HDR2.MH6 U1.A13 U1.A16 U1.AA4 U1.AA5 U1.AA6 U1.AA7 U1.AA8 U1.AA9 U1.AA10 U1.AA11 U1.AA14 U1.AA15 U1.AA18 U1.AA19 U1.AA20 U1.AA21 U1.AA22 U1.AA23 U1.AA24 U1.AB3 U1.AB4 U1.AB5 U1.AB6 U1.AB7 U1.AB8 U1.AB9 U1.AB10 U1.AB11 U1.AB12 U1.AB17 U1.AB18 U1.AB19 U1.AB20 U1.AB21 U1.AB22 U1.AB23 U1.AB24 U1.AB25 U1.AB26 U1.AC1 U1.AC2 U1.AC3 U1.AC4 U1.AC5 U1.AC6 U1.AC7 U1.AC8 U1.AC9 U1.AC10 U1.AC11 U1.AC13 U1.AC19 U1.AC20 U1.AC21 U1.AC22 U1.AC23 U1.AC24 U1.AC25 U1.AC26 U1.AC27 U1.AC28 U1.AD1 U1.AD2 U1.AD3 U1.AD4 U1.AD5 U1.AD7 U1.AD8 U1.AD10 U1.AD12 U1.AD13 U1.AD16 U1.AD17 U1.AD24 U1.AD25 U1.AD26 U1.AD27 U1.AD28 U1.AE1 U1.AE2 U1.AE11 U1.AE12 U1.AE13 U1.AE16 U1.AE17 U1.AE19 U1.AE25 U1.AE26 U1.AE27 U1.AE28 U1.AF1 U1.AF2 U1.AF7 U1.AF12 U1.AF13 U1.AF16 U1.AF17 U1.AF27 U1.AF28 U1.AG12 U1.AG13 U1.AG16 U1.AG17 U1.AH13 U1.AH16 U1.AH18 U1.B12 U1.B13 U1.B16 U1.B17 U1.C1 U1.C2 U1.C7 U1.C8 U1.C9 U1.C10 U1.C12 U1.C13 U1.C16 U1.C17 U1.C27 U1.C28 U1.D1 U1.D2 U1.D3 U1.D4 U1.D7 U1.D9 U1.D10 U1.D11 U1.D12 U1.D13 U1.D15 U1.D16 U1.D17 U1.D25 U1.D26 U1.D27 U1.D28 U1.E1 U1.E2 U1.E3 U1.E4 U1.E5 U1.E6 U1.E8 U1.E10 U1.E11 U1.E12 U1.E13 U1.E15 U1.E16 U1.E17 U1.E21 U1.E22 U1.E23 U1.E25 U1.E26 U1.E27 U1.E28 U1.F1 U1.F2 U1.F3 U1.F4 U1.F5 U1.F6 U1.F7 U1.F8 U1.F9 U1.F10 U1.F11 U1.F12 U1.F18 U1.F20 U1.F21 U1.F22 U1.F23 U1.F24 U1.F25 U1.F26 U1.F27 U1.F28 U1.G3 U1.G4 U1.G5 U1.G6 U1.G7 U1.G8 U1.G9 U1.G10 U1.G11 U1.G12 U1.G18 U1.G19 U1.G21 U1.G22 U1.G23 U1.G24 U1.G25 U1.G26 U1.H5 U1.H6 U1.H7 U1.H8 U1.H9 U1.H10 U1.H11 U1.H14 U1.H15 U1.H17 U1.H18 U1.H19 U1.H20 U1.H21 U1.H22 U1.H23 U1.H24 U1.J5 U1.J6 U1.J7 U1.J8 U1.J9 U1.J10 U1.J11 U1.J12 U1.J13 U1.J16 U1.J17 U1.J18 U1.J19 U1.J20 U1.J21 U1.J22 U1.J23 U1.J24 U1.K5 U1.K6 U1.K7 U1.K8 U1.K10 U1.K11 U1.K14 U1.K15 U1.K16 U1.K18 U1.K19 U1.K21 U1.K22 U1.K23 U1.K24 U1.L5 U1.L6 U1.L7 U1.L8 U1.L9 U1.L10 U1.L11 U1.L13 U1.L17 U1.L18 U1.L19 U1.L20 U1.L21 U1.L22 U1.L23 U1.L24 U1.M5 U1.M6 U1.M7 U1.M8 U1.M9 U1.M10 U1.M11 U1.M12 U1.M18 U1.M19 U1.M20 U1.M21 U1.M22 U1.M23 U1.N5 U1.N6 U1.N7 U1.N8 U1.N9 U1.N10 U1.N19 U1.N20 U1.N21 U1.N22 U1.N23 U1.N24 U1.N26 U1.P19 U1.R10 U1.T5 U1.T6 U1.T7 U1.T8 U1.T9 U1.T10 U1.T19 U1.T20 U1.T21 U1.T22 U1.T23 U1.U5 U1.U7 U1.U8 U1.U9 U1.U10 U1.U19 U1.U20 U1.U21 U1.U22 U1.U24 U1.U25 U1.V7 U1.V8 U1.V9 U1.V10 U1.V11 U1.V18 U1.V19 U1.V20 U1.V21 U1.V22 U1.W3 U1.W5 U1.W7 U1.W8 U1.W10 U1.W12 U1.W14 U1.W15 U1.W16 U1.W18 U1.W19 U1.W21 U1.W22 U1.W23 U1.W25 U1.Y5 U1.Y6 U1.Y7 U1.Y8 U1.Y9 U1.Y10 U1.Y11 U1.Y13 U1.Y16 U1.Y17 U1.Y18 U1.Y19 U1.Y20 U1.Y21 U1.Y22 U1.Y23 U1.Y24 U2.1 U5.1 U5.5 U5.9 U5.13 U5.16
copper on no net: | length 3.5
  Bottom Layer w0.254: 50.5,62.5 54,62.5

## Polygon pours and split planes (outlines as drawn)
VCC on Top Layer "Top Layer-VCC" (solid, remove dead copper, pour order 1000): 68.77,-0.049 68.77,82.651 -1.63,82.651 -1.63,0.155 68.77,0.155
GND on Bottom Layer "Bottom Layer-GND" (solid, remove dead copper, pour order 1001): 0.376,0.235 68.776,0.235 68.776,80.335 0.176,80.335 0.176,0.235
VCC on VCC_PLANE (split plane): 36.236,80.481 37.971,80.451 39.707,80.401 41.441,80.331 43.174,80.24 44.907,80.13 46.638,80 48.367,79.85 50.095,79.68 51.82,79.49 53.543,79.28 55.264,79.05 56.982,78.8 58.696,78.53 60.408,78.241 62.116,77.932 63.82,77.603 65.521,77.255 67.217,76.887 68.489,76.595 68.489,0.511 0.511,0.511 0.511,76.595 1.783,76.887 3.479,77.255 5.18,77.603 6.884,77.932 8.592,78.241 10.304,78.53 12.018,78.8 13.736,79.05 15.457,79.28 17.18,79.49 18.905,79.68 20.633,79.85 22.362,80 24.093,80.13 25.826,80.24 27.559,80.331 29.293,80.401 31.029,80.451 32.764,80.481 34.5,80.491
VCCINT on VCC_PLANE (split plane): 293 vertices, not listed, extent 13.756,6.556 59.844,60.044
VCCA_PLL1 on VCC_PLANE (split plane): 20.344,40.5 20.353,40.434 20.378,40.372 20.419,40.319 21.019,39.719 21.072,39.678 21.134,39.653 21.2,39.644 27.844,39.644 27.844,39.156 27.4,39.156 27.382,39.154 27.364,39.154 26.682,39.056 17.1,39.056 17.034,39.047 16.972,39.022 16.919,38.981 16.878,38.928 16.853,38.866 16.844,38.8 16.844,37.9 16.853,37.834 16.878,37.772 16.919,37.719 16.972,37.678 17.034,37.653 17.1,37.644 26.844,37.644 26.844,37.156 20.6,37.156 20.534,37.147 20.49,37.129 20.472,37.122 20.419,37.081 19.819,36.481 19.778,36.428 19.753,36.366 19.744,36.3 19.744,34.756 10.156,34.756 10.156,43.244 20.344,43.244
VCCA_PLL3 on VCC_PLANE (split plane): 60.144,39.856 57.9,39.856 57.834,39.847 57.772,39.822 57.719,39.781 57.678,39.728 57.653,39.666 57.644,39.6 57.644,35.856 56.5,35.856 56.434,35.847 56.372,35.822 56.319,35.781 56.278,35.728 56.253,35.666 56.244,35.6 56.244,34.36 49.756,34.453 49.756,36.5 49.756,36.502 49.756,36.504 49.752,36.535 49.747,36.566 49.747,36.568 49.746,36.57 49.734,36.599 49.722,36.628 49.721,36.63 49.72,36.632 49.42,37.132 49.4,37.156 49.381,37.181 49.379,37.182 49.378,37.184 49.353,37.203 49.328,37.222 49.326,37.223 49.324,37.224 49.295,37.235 49.266,37.247 49.264,37.248 49.262,37.249 49.231,37.252 49.2,37.256 48.2,37.256 48.191,37.255 48.183,37.256 48.158,37.251 48.134,37.247 48.126,37.244 48.117,37.243 48.095,37.231 48.072,37.222 48.065,37.217 48.057,37.213 48.039,37.196 48.019,37.181 48.014,37.174 48.007,37.169 47.386,36.459 42.784,36.554 42.256,36.932 42.256,37.944 54.5,37.944 54.566,37.953 54.628,37.978 54.681,38.019 54.722,38.072 54.747,38.134 54.756,38.2 54.756,38.5 54.747,38.566 54.722,38.628 54.681,38.681 54.628,38.722 54.566,38.747 54.5,38.756 42.256,38.756 42.256,39.605 43.318,40.844 47.844,40.844 47.844,40.2 47.853,40.134 47.871,40.09 47.878,40.072 47.919,40.019 48.219,39.719 48.272,39.678 48.334,39.653 48.391,39.645 48.4,39.644 49.1,39.644 49.131,39.648 49.162,39.651 49.164,39.652 49.166,39.653 49.195,39.665 49.224,39.676 49.226,39.677 49.228,39.678 49.253,39.697 49.278,39.716 49.279,39.718 49.281,39.719 49.3,39.744 49.32,39.768 49.62,40.268 49.621,40.27 49.622,40.272 49.634,40.301 49.646,40.33 49.647,40.332 49.647,40.334 49.652,40.365 49.656,40.396 49.656,40.398 49.656,40.4 49.656,42.544 60.144,42.544
VCCA_PLL5 on VCC_PLANE (split plane): 39.244,53.356 36.9,53.356 36.834,53.347 36.772,53.322 36.719,53.281 36.678,53.228 36.653,53.166 36.644,53.1 36.644,50.717 36.348,48.545 36.154,47.673 35.922,47.056 35.306,47.056 34.941,47.421 35.502,48.143 35.511,48.158 35.522,48.172 35.528,48.187 35.536,48.2 35.541,48.217 35.547,48.234 35.55,48.25 35.554,48.265 35.554,48.283 35.556,48.3 35.556,53.1 35.547,53.166 35.522,53.228 35.481,53.281 35.428,53.322 35.366,53.347 35.3,53.356 35.25,53.35 35.2,53.356 31.556,53.356 31.556,59.844 39.244,59.844
VCCA_PLL6 on VCC_PLANE (split plane): 35.844,24.7 35.853,24.634 35.878,24.572 35.919,24.519 35.972,24.478 36.034,24.453 36.1,24.444 37.844,24.444 37.844,23.656 35.8,23.656 35.734,23.647 35.672,23.622 35.619,23.581 35.578,23.528 35.553,23.466 35.544,23.4 35.544,18.656 31.956,18.656 31.956,23.444 33.5,23.444 33.526,23.447 33.552,23.449 33.559,23.452 33.566,23.453 33.591,23.463 33.616,23.471 33.621,23.475 33.628,23.478 33.649,23.494 33.671,23.509 33.675,23.514 33.681,23.519 33.697,23.54 33.714,23.56 33.718,23.566 33.722,23.572 33.732,23.596 33.743,23.62 33.745,23.627 33.747,23.634 33.751,23.66 33.756,23.686 33.942,27.044 35.844,27.044
GND on GND_PLANE (split plane): 36.236,80.481 37.971,80.451 39.707,80.401 41.441,80.331 43.174,80.24 44.907,80.13 46.638,80 48.367,79.85 50.095,79.68 51.82,79.49 53.543,79.28 55.264,79.05 56.982,78.8 58.696,78.53 60.408,78.241 62.116,77.932 63.82,77.603 65.521,77.255 67.217,76.887 68.489,76.595 68.489,0.511 0.511,0.511 0.511,76.595 1.783,76.887 3.479,77.255 5.18,77.603 6.884,77.932 8.592,78.241 10.304,78.53 12.018,78.8 13.736,79.05 15.457,79.28 17.18,79.49 18.905,79.68 20.633,79.85 22.362,80 24.093,80.13 25.826,80.24 27.559,80.331 29.293,80.401 31.029,80.451 32.764,80.481 34.5,80.491

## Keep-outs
Top Layer:
  circle w0.2: c10.4,21 r1.5
  circle w0.2: c61.8,53.6 r1.5
Bottom Layer:
  circle w0.2: c51.1,50.9 r1.5
  circle w0.2 net FPGA_CLK: c17.5,24.9 r1.5
  circle w0.2: c4.3,56.9 r1.5
  circle w0.2: c62.9,27.4 r1.5
Keep-Out Layer:
  the board outline again, w1.8

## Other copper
VCC_PLANE (plane layer: these items are gaps in the copper):
  lines w0.254: 36.6,60.1 39.5,60.1 ; 42,39.7 42.1,39.9 ; 49.4,42.8 49.5,42.8
  lines w0.508: 19.8,43.5 20.6,43.5 ; 35.2,53.1 34.5,53.1 31.3,53.1 31.3,60.1 39.5,60.1 39.5,53.1 36.9,53.1 36.9,50.7 36.6,48.5 36.4,47.6 36.1,46.8 35.2,46.8 34.6,47.4 35.3,48.3 35.3,53.1 ; 42,38.5 54.5,38.5 54.5,38.2 42,38.2 ; 49.4,42.8 49.4,40.4 49.1,39.9 48.4,39.9 48.1,40.2 48.1,41.1 43.2,41.1 42,39.7 42,38.2 ; 49.5,42.8 60.4,42.8 60.4,39.6 57.9,39.6 57.9,35.6 56.5,35.6 56.5,34.1 49.5,34.2 49.5,36.5 49.2,37 48.2,37 47.5,36.2 42.7,36.3 42,36.8 42,38.2 ; 20.6,43.5 9.9,43.5 9.9,34.5 20,34.5 20,36.3 20.6,36.9 27.1,36.9 27.1,37.9 17.1,37.9 17.1,38.8 26.7,38.8 27.4,38.9 28.1,38.9 28.1,39.9 21.2,39.9 20.6,40.5 20.6,43.5 ; 13.5,29.4 13.5,32 16.8,32 17.3,32.4 27.5,32.4 29.3,34.2 29.3,43.4 37.3,43.4 37.3,44.5 43.5,54 43.5,57.8 45.9,57.8 47.1,60.3 59,60.3 59,57 59,53.4 50.6,53.5 47.1,53.5 45.3,50.6 45.3,47.3 60.1,47.3 60.1,44.7 57.1,44.7 57.1,45.4 43,45.4 43,43.5 38.9,39.3 38.9,36.9 42.6,33.4 43.7,29.4 43.8,25.8 45.6,20.3 49.8,13.2 54.4,6.3 49.9,6.3 42.2,20.9 36.9,20.9 36.9,22.3 41.3,22.3 39.4,26.1 39.3,29.9 39.3,31.3 36.6,34.4 33.6,34.4 32.6,32.4 32.6,31.4 29.7,31.4 28,29.4 13.5,29.4 ; 31.7,18.4 31.7,23.7 33.5,23.7 33.7,27.3 36.1,27.3 36.1,24.7 38.1,24.7 38.1,23.4 35.8,23.4 35.8,18.4 31.7,18.4

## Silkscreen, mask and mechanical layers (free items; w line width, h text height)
Top Overlay:
  lines w0.08: 33.5,74.6 34.8,74.2 ; 34.079,40.221 34.079,41.92 ; 34.1,34 34.1,34.9 ; 43,75.1 43.5,75.9 ; 46.1,74.4 46.8,74.8 ; 51.1,73.2 51.7,73.2 ; 52.6,59.2 52.9,60.1 ; 53.4,71.2 54,71.2 ; 56.3,8.1 56.9,8.5 ; 62.5,49.7 63,50.1 ; 62.6,57.8 63.1,58.2
  text "(TMS)" at 46.2,75.7 h0.8
  text "(TCK)" at 49.4,74.5 h0.8
  text "(TDO)" at 30.8,73.1 h0.8
  text "(TDI)" at 54.6,72.8 h0.8
  text "(+3V3)" at 56.5,70.8 h0.8
  text "(+1V5)" at 55.4,59.9 h0.8
  text "(+5V)" at 63.2,56.5 h0.8
  text "(TRST)" at 63,48.6 h0.8
  text "(+5V)" at 57,6.8 h0.8
  text "(CONFIG)" at 17,1.8 h0.8
  text "(POWER)" at 47.3,1.8 h0.8
Bottom Overlay:
  drawing of 850 lines, arcs and shapes, not listed
  text "REV 1.00" at 47.6,76.5 h1.3
  text "NBP6" at 54.5,76.5 h1.3
  text "1" at 13.97,58.42 h1
  text "1" at 14.224,7.62 h1
PCB Boundary:
  the board outline again, w0.25
  text "PCB boundary coincides with centre-line of tracks and arc" at 0,-12 h0.75
Gerber ID:
  text ".Layer_Name" at 0,-13.8 h0.75
Printout ID:
  text ".Printout_Name" at 0,-10 h0.75
Drill Drawing:
  text ".Legend" at -0.2,-15.6 h0.75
